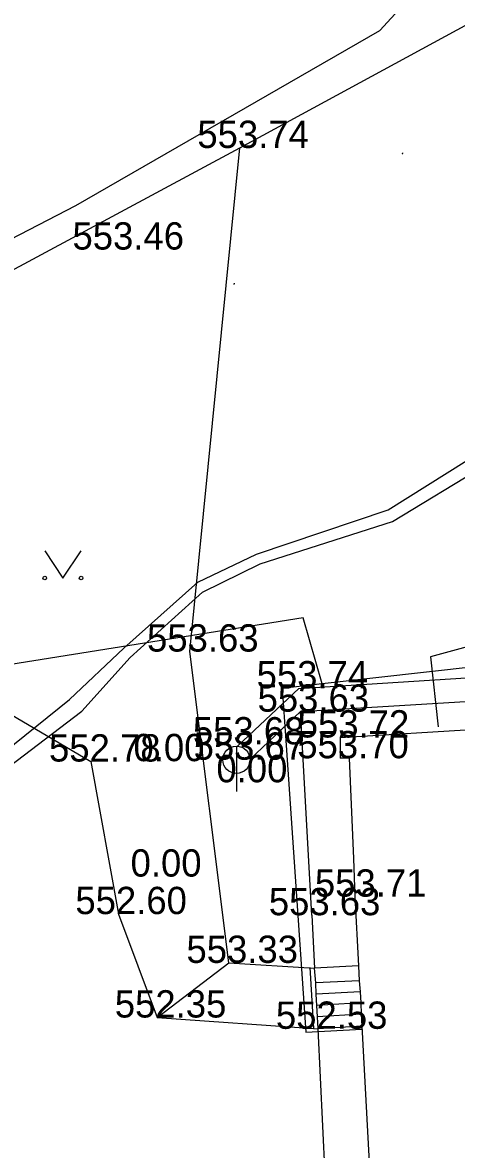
# Model space of a CAD drawing. Extents: x -669393 to -668650, y -1126925 to -1126294.
# Drawn here: x -669272.02 to -669260.09, y -1126465.9 to -1126434.96 of the extents above; entities that cross this region are included whole.
import ezdxf

# ---------------------------------------------------------------- set-up
doc = ezdxf.new("R2010")
doc.units = 0
for name, color, linetype in [('G_Bod_tecka', 7, 'Continuous'), ('G_Bod_vyska', 7, 'Continuous'), ('G_Breh_Teren', 7, 'Continuous'), ('G_Budovy_Objekty', 7, 'Continuous'), ('G_Budovy_vstupy', 7, 'Continuous'), ('G_Cesty_Schody', 7, 'Continuous'), ('G_Plochy_zpevnene', 7, 'Continuous'), ('G_Ploty', 7, 'Continuous'), ('G_Site-kanalizace', 7, 'Continuous'), ('G_Vyskopis-bod_terenu', 7, 'Continuous'), ('G_Z_ELsilove_podz_kotovane', 7, 'Continuous'), ('G_Z_PLYNY_podz_geodeticky', 7, 'Continuous'), ('G_Z_SPOJE_podz_geodeticky', 7, 'Continuous'), ('G_Z_SPOJE_podz_kotovane', 7, 'Continuous'), ('G_Z_SPOJE_podz_priblizne', 7, 'Continuous'), ('G_Zabradli_Svodidla', 7, 'Continuous'), ('G_Zelen-Znacky', 7, 'Continuous')]:
    doc.layers.add(name, color=color, linetype=linetype)

msp = doc.modelspace()

# ---------------------------------------------------------------- linework, layer by layer
at = {"layer": 'G_Bod_tecka'}
for p, q in [((-669266.05, -1126438.4), (-669266.05, -1126438.4)), ((-669269.47, -1126441.19), (-669269.47, -1126441.19)), ((-669267.42, -1126452.23), (-669267.42, -1126452.23)), ((-669264.42, -1126453.24), (-669264.42, -1126453.24)), ((-669264.38, -1126453.88), (-669264.38, -1126453.88)), ((-669263.29, -1126454.59), (-669263.29, -1126454.59)), ((-669266.16, -1126454.78), (-669266.16, -1126454.78)), ((-669266.14, -1126455.2), (-669266.14, -1126455.2)), ((-669263.29, -1126455.16), (-669263.29, -1126455.16)), ((-669270.14, -1126455.25), (-669270.14, -1126455.25)), ((-669268.2, -1126455.24), (-669268.2, -1126455.24)), ((-669265.91, -1126455.82), (-669265.91, -1126455.82)), ((-669268.28, -1126458.41), (-669268.28, -1126458.41)), ((-669262.88, -1126458.96), (-669262.88, -1126458.96)), ((-669269.38, -1126459.44), (-669269.38, -1126459.44)), ((-669264.07, -1126459.47), (-669264.07, -1126459.47)), ((-669266.35, -1126460.78), (-669266.35, -1126460.78)), ((-669268.32, -1126462.28), (-669268.32, -1126462.28)), ((-669263.89, -1126462.59), (-669263.89, -1126462.59))]:
    msp.add_line(p, q, dxfattribs=at)
at = {"layer": 'G_Breh_Teren'}
for p, q in [((-669267.42, -1126452.23), (-669266.05, -1126438.4)), ((-669279.37, -1126449.83), (-669270.14, -1126455.25)), ((-669266.35, -1126460.78), (-669267.42, -1126452.23)), ((-669270.14, -1126455.25), (-669269.38, -1126459.44)), ((-669269.38, -1126459.44), (-669268.32, -1126462.28)), ((-669268.32, -1126462.28), (-669266.35, -1126460.78)), ((-669266.35, -1126460.78), (-669263.99, -1126460.92)), ((-669268.32, -1126462.28), (-669263.89, -1126462.59))]:
    msp.add_line(p, q, dxfattribs=at)
at = {"layer": 'G_Budovy_Objekty'}
for p, q in [((-669263.29, -1126454.59), (-669259.07, -1126454.33)), ((-669263.29, -1126454.59), (-669263.29, -1126455.16)), ((-669263.04, -1126455.16), (-669263.29, -1126455.16)), ((-669263.04, -1126455.16), (-669262.92, -1126457.91)), ((-669262.88, -1126458.96), (-669262.78, -1126460.86)), ((-669262.78, -1126460.86), (-669262.76, -1126461.27)), ((-669262.76, -1126461.27), (-669262.74, -1126461.57)), ((-669262.74, -1126461.57), (-669262.72, -1126461.88)), ((-669262.72, -1126461.88), (-669262.71, -1126462.19)), ((-669262.71, -1126462.19), (-669262.69, -1126462.52)), ((-669262.69, -1126462.52), (-669262.28, -1126470.3))]:
    msp.add_line(p, q, dxfattribs=at)
at = {"layer": 'G_Budovy_vstupy'}
msp.add_line((-669262.92, -1126457.91), (-669262.88, -1126458.96), dxfattribs=at)
at = {"layer": 'G_Cesty_Schody'}
for p, q in [((-669264.38, -1126453.88), (-669248.65, -1126452.9)), ((-669262.78, -1126460.86), (-669263.99, -1126460.92)), ((-669263.96, -1126461.33), (-669263.99, -1126460.92)), ((-669262.76, -1126461.27), (-669263.96, -1126461.33)), ((-669263.95, -1126461.64), (-669263.96, -1126461.33)), ((-669262.74, -1126461.57), (-669263.95, -1126461.64)), ((-669263.93, -1126461.95), (-669263.95, -1126461.64)), ((-669262.72, -1126461.88), (-669263.93, -1126461.95)), ((-669263.91, -1126462.26), (-669263.93, -1126461.95)), ((-669262.71, -1126462.19), (-669263.91, -1126462.26)), ((-669263.89, -1126462.59), (-669263.91, -1126462.26)), ((-669262.69, -1126462.52), (-669263.89, -1126462.59))]:
    msp.add_line(p, q, dxfattribs=at)
at = {"layer": 'G_Plochy_zpevnene'}
for p, q in [((-669264.42, -1126453.24), (-669249.28, -1126452.3)), ((-669264.42, -1126453.24), (-669266.11, -1126454.83)), ((-669264.38, -1126453.88), (-669265.77, -1126455.19)), ((-669264.07, -1126459.47), (-669264.38, -1126453.88)), ((-669264.07, -1126459.47), (-669263.99, -1126460.92)), ((-669263.6, -1126468.56), (-669263.89, -1126462.59))]:
    msp.add_line(p, q, dxfattribs=at)
at = {"layer": 'G_Ploty'}
for p, q in [((-669266.05, -1126438.4), (-669259.75, -1126434.98)), ((-669276.9, -1126444.22), (-669266.05, -1126438.4))]:
    msp.add_line(p, q, dxfattribs=at)
at = {"layer": 'G_Site-kanalizace'}
msp.add_line((-669266.14, -1126454.825), (-669266.14, -1126456.075), dxfattribs=at)
msp.add_circle((-669266.14, -1126455.2), 0.375, dxfattribs=at)
at = {"layer": 'G_Vyskopis-bod_terenu'}
for p, q in [((-669261.58, -1126438.55), (-669261.56, -1126438.55)), ((-669261.57, -1126438.535), (-669261.57, -1126438.55)), ((-669261.57, -1126438.565), (-669261.57, -1126438.55)), ((-669266.21, -1126442.13), (-669266.19, -1126442.13)), ((-669266.2, -1126442.115), (-669266.2, -1126442.13)), ((-669266.2, -1126442.145), (-669266.2, -1126442.13))]:
    msp.add_line(p, q, dxfattribs=at)
at = {"layer": 'G_Z_ELsilove_podz_kotovane'}
for points in [[(-669294.238, -1126484.98), (-669293.805, -1126479.917), (-669293.311, -1126474.694), (-669293.134, -1126470.841), (-669292.916, -1126470.242), (-669292.754, -1126468.991), (-669292.213, -1126467.442), (-669291.269, -1126465.924), (-669289.953, -1126465.075), (-669287.478, -1126464.367), (-669282.756, -1126462.731), (-669280.311, -1126461.704), (-669278.03, -1126460.039), (-669274.204, -1126456.763), (-669270.394, -1126453.865), (-669269.061, -1126452.394), (-669267.07, -1126450.598), (-669265.489, -1126449.819), (-669261.844, -1126448.654), (-669256.767, -1126445.579), (-669255.918, -1126444.71), (-669255.346, -1126442.068), (-669255.801, -1126437.981), (-669255.665, -1126434.767)], [(-669294.703, -1126484.965), (-669294.159, -1126479.826), (-669293.773, -1126474.673), (-669293.472, -1126470.855), (-669293.268, -1126470.321), (-669293.146, -1126469.122), (-669292.654, -1126467.249), (-669291.4, -1126465.552), (-669290.24, -1126464.796), (-669287.41, -1126463.964), (-669282.924, -1126462.475), (-669280.401, -1126461.24), (-669278.377, -1126459.795), (-669274.375, -1126456.475), (-669270.731, -1126453.546), (-669269.236, -1126452.137), (-669267.198, -1126450.324), (-669265.586, -1126449.552), (-669261.964, -1126448.337), (-669257.103, -1126445.287), (-669256.5, -1126444.406), (-669255.97, -1126442.335), (-669256.127, -1126438.463), (-669256.083, -1126434.882)]]:
    msp.add_lwpolyline(points, dxfattribs=at)
at = {"layer": 'G_Z_PLYNY_podz_geodeticky'}
msp.add_lwpolyline([(-669242.9, -1126447.32), (-669247.73, -1126448.82), (-669248.74, -1126449.1), (-669250.19, -1126449.49), (-669251.01, -1126449.71), (-669260.8, -1126452.37), (-669260.59, -1126454.3)], dxfattribs=at)
at = {"layer": 'G_Z_SPOJE_podz_geodeticky'}
for points in [[(-669263.78, -1126453.12), (-669264.3, -1126451.3), (-669291.99, -1126455.72), (-669300.48, -1126462.06), (-669302.48, -1126463.41), (-669301.93, -1126471.1)], [(-669249.52, -1126451.52), (-669263.78, -1126453.12)], [(-669263.78, -1126453.12), (-669264.88, -1126453.24), (-669264.78, -1126454.67), (-669264.23, -1126462.68), (-669262.69, -1126462.6)]]:
    msp.add_lwpolyline(points, dxfattribs=at)
at = {"layer": 'G_Z_SPOJE_podz_kotovane'}
for points in [[(-669301.38, -1126453.09), (-669285.95, -1126447.98), (-669284.44, -1126446.68), (-669282.62, -1126446.21), (-669270.56, -1126439.98), (-669262.2, -1126435.17), (-669260.95, -1126433.81), (-669259.64, -1126432.53), (-669259.88, -1126429.32), (-669259.99, -1126428.23), (-669259.52, -1126426.66), (-669259.651, -1126424.833)], [(-669263.78, -1126453.12), (-669264.3, -1126451.3), (-669291.99, -1126455.72), (-669300.48, -1126462.06), (-669302.48, -1126463.41), (-669301.93, -1126471.1)], [(-669249.52, -1126451.52), (-669263.78, -1126453.12)], [(-669263.78, -1126453.12), (-669264.88, -1126453.24), (-669264.78, -1126454.67), (-669264.23, -1126462.68), (-669262.69, -1126462.6)]]:
    msp.add_lwpolyline(points, dxfattribs=at)
at = {"layer": 'G_Z_SPOJE_podz_priblizne'}
for points in [[(-669263.78, -1126453.12), (-669264.3, -1126451.3), (-669291.99, -1126455.72), (-669300.48, -1126462.06), (-669302.48, -1126463.41), (-669301.93, -1126471.1)], [(-669249.52, -1126451.52), (-669263.78, -1126453.12)], [(-669263.78, -1126453.12), (-669264.88, -1126453.24), (-669264.78, -1126454.67), (-669264.23, -1126462.68), (-669262.69, -1126462.6)]]:
    msp.add_lwpolyline(points, dxfattribs=at)
at = {"layer": 'G_Zabradli_Svodidla'}
msp.add_line((-669264.01, -1126462.58), (-669264.11, -1126460.91), dxfattribs=at)
at = {"layer": 'G_Zelen-Znacky'}
for p, q in [((-669271.41, -1126449.46), (-669270.91, -1126450.21)), ((-669270.91, -1126450.21), (-669270.41, -1126449.46))]:
    msp.add_line(p, q, dxfattribs=at)
for centre in [(-669271.41, -1126450.21), (-669270.41, -1126450.21)]:
    msp.add_circle(centre, 0.05, dxfattribs=at)

# ---------------------------------------------------------------- texts
at = {"layer": 'G_Bod_vyska'}
for s, p in [('553.74', (-669267.214, -1126438.4)), ('553.46', (-669270.648, -1126441.19)), ('553.63', (-669268.598, -1126452.23)), ('553.74', (-669265.584, -1126453.24)), ('553.63', (-669265.558, -1126453.88)), ('553.72', (-669264.454, -1126454.59)), ('553.68', (-669267.338, -1126454.78)), ('552.78', (-669271.294, -1126455.25)), ('0.00', (-669268.97, -1126455.24)), ('553.67', (-669267.318, -1126455.2)), ('553.70', (-669264.466, -1126455.16)), ('0.00', (-669266.69, -1126455.82)), ('0.00', (-669269.05, -1126458.41)), ('553.71', (-669263.982, -1126458.96)), ('552.60', (-669270.569, -1126459.44)), ('553.63', (-669265.248, -1126459.47)), ('553.33', (-669267.514, -1126460.78)), ('552.35', (-669269.484, -1126462.28)), ('552.53', (-669265.054, -1126462.59))]:
    msp.add_text(s, height=0.75, dxfattribs=at).set_placement(p)

doc.saveas('drawing.dxf')
